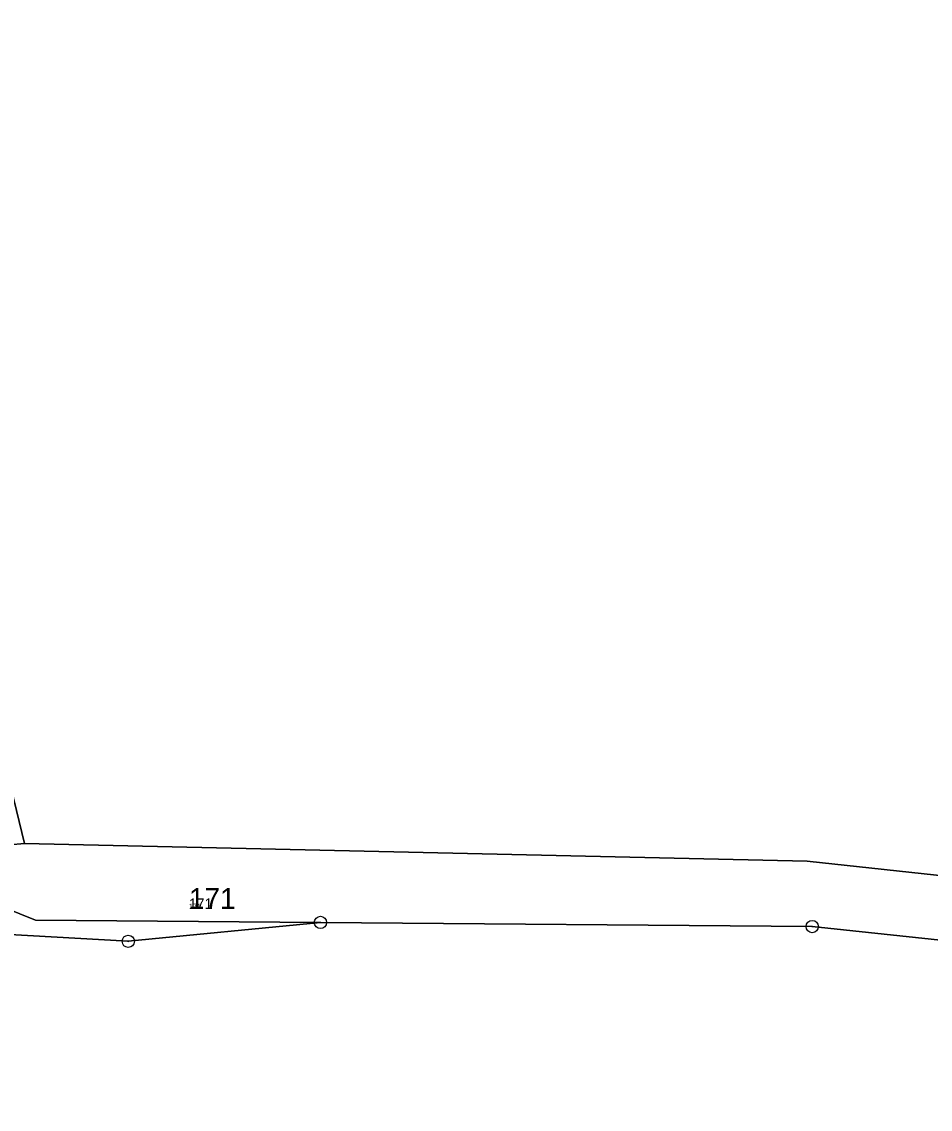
# Model space of a CAD drawing. Extents: x -759873 to -758487, y -975024 to -973516.
# Drawn here: x -759456.7 to -759382.7, y -974563.6 to -974475 of the extents above; entities that cross this region are included whole.
import ezdxf

# ---------------------------------------------------------------- set-up
doc = ezdxf.new("R2010")
doc.units = 0
for name, color, linetype in [('KAT_02_hranice parcel', 7, 'Continuous'), ('KAT_03_1000_čísla parcelní', 7, 'Continuous'), ('KAT_03_250_čísla parcelní', 7, 'Continuous'), ('KAT_03_500_čísla parcelní', 7, 'Continuous'), ('KAT_11_značky bodu BP', 7, 'Continuous'), ('KAT_14_plocha_pozemek', 7, 'Continuous')]:
    doc.layers.add(name, color=color, linetype=linetype)

msp = doc.modelspace()

# ---------------------------------------------------------------- linework, layer by layer
at = {"layer": 'KAT_02_hranice parcel'}
msp.add_line((-759462.56, -974542.46), (-759456.43, -974541.94), dxfattribs=at)
for points in [[(-759513.7, -974388.36), (-759504.64, -974393.1), (-759481.61, -974430.04), (-759469.74, -974487.16), (-759456.43, -974541.94)], [(-759456.43, -974541.94), (-759392.7, -974543.37), (-759351.8, -974547.79)], [(-759461.67, -974545.71), (-759455.54, -974548.17), (-759432.33, -974548.36)], [(-759468.78, -974548.5), (-759462.01, -974549.11), (-759447.98, -974549.9), (-759432.33, -974548.36)], [(-759432.33, -974548.36), (-759392.27, -974548.7), (-759357.85, -974552.36)]]:
    msp.add_lwpolyline(points, dxfattribs=at)
at = {"layer": 'KAT_11_značky bodu BP'}
for centre, radius in [((-759432.33, -974548.36), 0.5), ((-759432.33, -974548.36), 0.0303), ((-759392.27, -974548.7), 0.5), ((-759392.27, -974548.7), 0.0303), ((-759447.98, -974549.9), 0.5), ((-759447.98, -974549.9), 0.0303)]:
    msp.add_circle(centre, radius, dxfattribs=at)
at = {"layer": 'KAT_14_plocha_pozemek'}
for points in [[(-759485.97, -974434.88), (-759471.83, -974495.63), (-759462.56, -974542.46), (-759456.43, -974541.94), (-759469.74, -974487.16), (-759481.61, -974430.04)], [(-759481.61, -974430.04), (-759469.74, -974487.16), (-759456.43, -974541.94), (-759392.7, -974543.37), (-759351.8, -974547.79), (-759352.33, -974538.42), (-759364.28, -974508.82), (-759380.34, -974471.16)], [(-759351.8, -974547.79), (-759392.7, -974543.37), (-759456.43, -974541.94), (-759462.56, -974542.46)], [(-759461.67, -974545.71), (-759455.54, -974548.17), (-759432.33, -974548.36), (-759392.27, -974548.7), (-759357.85, -974552.36)], [(-759459.82, -974591.36), (-759444.22, -974592.7), (-759424.58, -974592.4), (-759405.56, -974590.95), (-759390.95, -974590), (-759382.8, -974590.19), (-759370.19, -974589.29), (-759355.46, -974587.9), (-759353.14, -974590.15), (-759351.99, -974590.04), (-759353.67, -974578.05), (-759357.85, -974552.36), (-759392.27, -974548.7), (-759432.33, -974548.36), (-759447.98, -974549.9), (-759462.01, -974549.11)]]:
    msp.add_lwpolyline(points, dxfattribs=at)
msp.add_lwpolyline([(-759432.33, -974548.36), (-759455.54, -974548.17), (-759461.67, -974545.71), (-759468.78, -974548.5), (-759462.01, -974549.11), (-759447.98, -974549.9)], close=True, dxfattribs=at)

# ---------------------------------------------------------------- texts
at = {"layer": 'KAT_03_1000_čísla parcelní'}
msp.add_text('171', height=1.7, dxfattribs=at).set_placement((-759443.04, -974547.26))
at = {"layer": 'KAT_03_250_čísla parcelní'}
msp.add_text('171', height=0.425, dxfattribs=at).set_placement((-759443.04, -974547.26))
at = {"layer": 'KAT_03_500_čísla parcelní'}
msp.add_text('171', height=0.85, dxfattribs=at).set_placement((-759443.04, -974547.26))

doc.saveas('drawing.dxf')
